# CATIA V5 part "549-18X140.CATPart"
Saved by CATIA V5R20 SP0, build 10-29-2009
Part number: 549-18X140
Definition: NONE
Nomenclature: 549-18X140
Source: Unknown
Description: 549-18X140
Bounding box of the stored display mesh (mm): x 0 to 140, y -10.5 to 10.5, z -10.5 to 10.5
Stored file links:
  C:\Users\Utente\Desktop\IO LAVORO\3D X SITO CF\X SITO\PLASTICA\549\549-18X140.CATPart
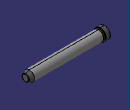
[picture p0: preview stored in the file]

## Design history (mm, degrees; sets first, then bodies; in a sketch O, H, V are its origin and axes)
Body1 "549-18X140" (main body)
  Solid1: solid without history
